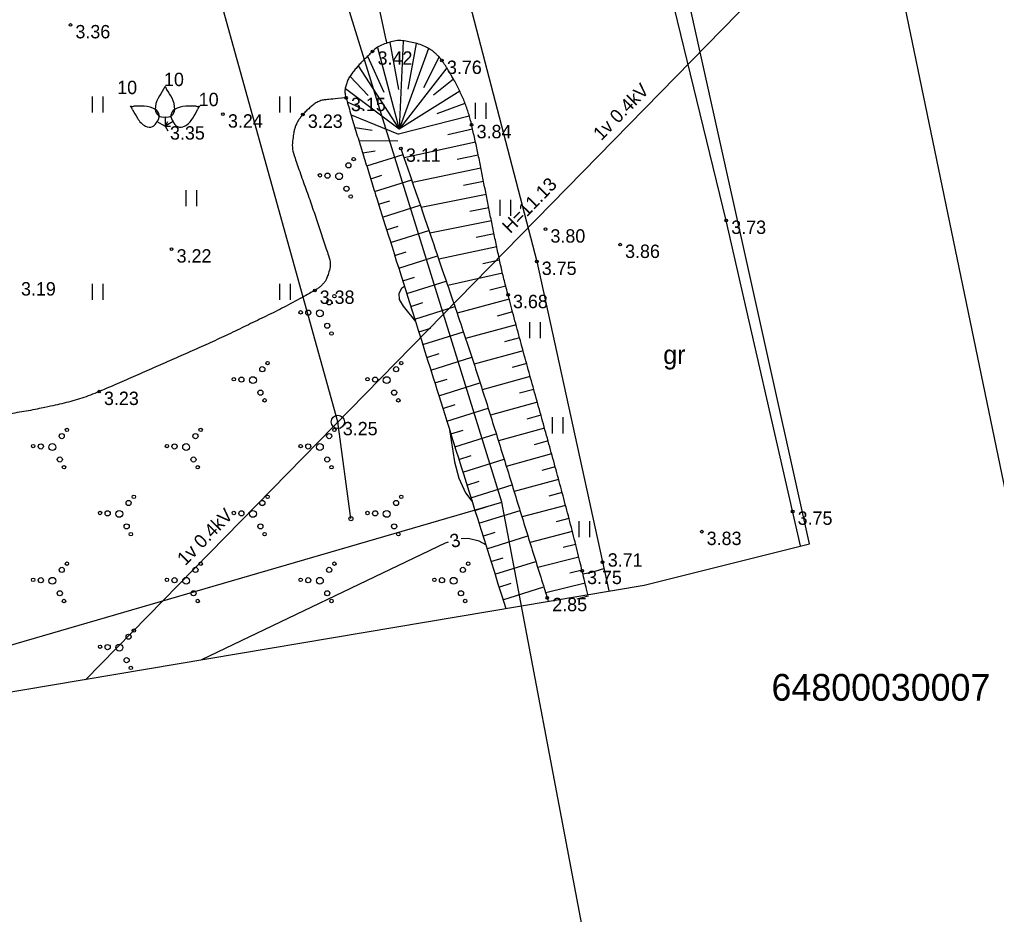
# Model space of a CAD drawing. Extents: x 321079 to 321220, y 257030 to 257220.
# Drawn here: x 321153.77 to 321190.3, y 257097.53 to 257130.98 of the extents above; entities that cross this region are included whole.
import ezdxf

# ---------------------------------------------------------------- set-up
doc = ezdxf.new("R2010")
doc.units = 0
for name, color, linetype in [('CELI_CMAL_####_####_#', 7, 'Continuous'), ('CELI_CSEG_####_TKST_#', 7, 'Continuous'), ('ELEK_ELEM_####_####_#', 7, 'Continuous'), ('ELEK_SAIT_####_####_#', 7, 'Continuous'), ('ELEK_VADV_ZSPR_####_#', 7, 'Continuous'), ('ELEK_VADV_ZSPR_TKST_#', 7, 'Continuous'), ('RAMI_UZMR_####_####_#', 7, 'Continuous'), ('RELJ_AATZ_####_TKST_#', 7, 'Continuous'), ('RELJ_ELEM_####_####_#', 7, 'Continuous'), ('RELJ_HORZ_####_TKST_#', 7, 'Continuous'), ('RELJ_HORZ_PAMT_####_#', 7, 'Continuous'), ('RELJ_HORZ_PUSH_####_#', 7, 'Continuous'), ('RELJ_NOGA_####_####_#', 7, 'Continuous'), ('RELJ_NOGL_####_####_#', 7, 'Continuous'), ('ROBZ_KADS_####_TKST_#', 7, 'Continuous'), ('ROBZ_UZMR_####_####_#', 7, 'Continuous'), ('TERT_DIAM_####_TKST_#', 7, 'Continuous'), ('TERT_ELEM_####_####_#', 7, 'Continuous'), ('TERT_KONT_####_####_#', 7, 'Continuous')]:
    doc.layers.add(name, color=color, linetype=linetype)

msp = doc.modelspace()

# ---------------------------------------------------------------- linework, layer by layer
at = {"layer": 'CELI_CMAL_####_####_#'}
for points in [[(321182.971, 257111.303), (321180.196, 257123.466), (321177.038, 257136.408), (321174.394, 257148.502), (321172.25, 257161.008)], [(321164.229, 257149.382), (321166.166, 257146.657), (321169.755, 257134.824), (321173.111, 257121.931), (321175.798, 257109.619)]]:
    msp.add_lwpolyline(points, dxfattribs=at)
at = {"layer": 'ELEK_ELEM_####_####_#'}
for centre, radius in [((321165.672, 257115.939), 0.25), ((321165.672, 257115.939), 0.0225), ((321166.162, 257112.322), 0.075)]:
    msp.add_circle(centre, radius, dxfattribs=at)
at = {"layer": 'ELEK_SAIT_####_####_#'}
msp.add_line((321166.162, 257112.322), (321165.672, 257115.939), dxfattribs=at)
at = {"layer": 'ELEK_VADV_ZSPR_####_#'}
for p, q in [((321165.672, 257115.939), (321155.067, 257154.09)), ((321190.982, 257141.796), (321156.234, 257106.297))]:
    msp.add_line(p, q, dxfattribs=at)
at = {"layer": 'RAMI_UZMR_####_####_#'}
msp.add_lwpolyline([(321107.5, 257141.5), (321108.611, 257133.395), (321131.584, 257099.382), (321150.327, 257105.322), (321177.121, 257109.842), (321183.308, 257111.386), (321177.517, 257137.442), (321172.561, 257161.05), (321156.27, 257158.872), (321156.852, 257154.517), (321139.352, 257150.329), (321114.57, 257145.337)], close=True, dxfattribs=at)
at = {"layer": 'RELJ_ELEM_####_####_#'}
for centre in [(321155.676, 257130.776), (321166.972, 257129.79), (321169.565, 257129.445), (321165.978, 257128.056), (321161.378, 257127.439), (321164.367, 257127.43), (321170.675, 257127.041), (321168.031, 257126.162), (321180.196, 257123.466), (321173.436, 257123.14), (321159.459, 257122.394), (321176.226, 257122.566), (321173.111, 257121.931), (321164.809, 257120.851), (321172.035, 257120.69), (321156.743, 257117.07), (321182.677, 257112.592), (321179.277, 257111.836), (321175.564, 257110.692), (321174.805, 257110.376), (321173.503, 257109.362)]:
    msp.add_circle(centre, 0.05, dxfattribs=at)
at = {"layer": 'RELJ_HORZ_PAMT_####_#'}
for points in [[(321169.793, 257111.444), (321169.686, 257111.408), (321160.579, 257107.051)], [(321171.203, 257111.339), (321170.955, 257111.479), (321170.543, 257111.58), (321170.279, 257111.565)]]:
    msp.add_lwpolyline(points, dxfattribs=at)
at = {"layer": 'RELJ_HORZ_PUSH_####_#'}
for points in [[(321167.176, 257131.552), (321167.47, 257130.219), (321167.505, 257130.094)], [(321168.161, 257121.006), (321168.057, 257120.93), (321167.951, 257120.735), (321167.971, 257120.513), (321168.117, 257120.265), (321168.573, 257119.697)], [(321169.85, 257115.639), (321170.038, 257114.442), (321170.191, 257113.832), (321170.451, 257113.287), (321170.688, 257112.976)], [(321174.834, 257110.255), (321175.166, 257110.321), (321175.614, 257110.462)]]:
    msp.add_lwpolyline(points, dxfattribs=at)
at = {"layer": 'RELJ_NOGA_####_####_#'}
for p, q in [((321167.617, 257130.126), (321167.936, 257128.366)), ((321168.113, 257130.169), (321167.969, 257126.878)), ((321168.605, 257130.085), (321168.284, 257128.376)), ((321166.784, 257129.605), (321167.392, 257128.259)), ((321167.158, 257129.935), (321167.969, 257126.878)), ((321169.065, 257129.892), (321167.969, 257126.878)), ((321169.455, 257129.583), (321168.876, 257128.427)), ((321166.434, 257129.248), (321167.969, 257126.878)), ((321166.134, 257128.849), (321166.808, 257128.134)), ((321169.742, 257129.174), (321167.969, 257126.878)), ((321170, 257128.746), (321169.248, 257128.149)), ((321167.969, 257126.878), (321165.964, 257128.386)), ((321170.229, 257128.302), (321167.969, 257126.878)), ((321166.026, 257127.898), (321166.64, 257127.616)), ((321170.424, 257127.842), (321169.372, 257127.455)), ((321166.17, 257127.419), (321167.942, 257126.691)), ((321170.588, 257127.37), (321167.942, 257126.691)), ((321166.314, 257126.94), (321166.956, 257126.845)), ((321170.71, 257126.885), (321169.789, 257126.666)), ((321166.458, 257126.462), (321167.913, 257126.45)), ((321170.817, 257126.397), (321168.152, 257125.807)), ((321167.073, 257126.063), (321166.605, 257125.984)), ((321166.751, 257125.506), (321168.111, 257125.929)), ((321170.922, 257125.908), (321170.136, 257125.746)), ((321171.023, 257125.418), (321168.464, 257124.892)), ((321166.9, 257125.028), (321167.311, 257125.156)), ((321167.048, 257124.551), (321168.434, 257124.982)), ((321171.121, 257124.928), (321170.371, 257124.779)), ((321167.197, 257124.073), (321167.616, 257124.204)), ((321171.218, 257124.437), (321168.784, 257123.955)), ((321167.347, 257123.596), (321168.755, 257124.039)), ((321171.315, 257123.947), (321170.605, 257123.806)), ((321171.412, 257123.456), (321169.109, 257123)), ((321167.497, 257123.119), (321167.923, 257123.253)), ((321167.647, 257122.642), (321169.078, 257123.093)), ((321171.514, 257122.967), (321170.844, 257122.826)), ((321167.797, 257122.165), (321168.23, 257122.302)), ((321171.617, 257122.477), (321169.443, 257122.022)), ((321167.947, 257121.689), (321169.401, 257122.146)), ((321171.722, 257121.989), (321171.091, 257121.845)), ((321168.097, 257121.212), (321168.537, 257121.35)), ((321168.247, 257120.735), (321169.723, 257121.199)), ((321171.833, 257121.501), (321169.78, 257121.033)), ((321171.954, 257121.016), (321171.354, 257120.866)), ((321172.078, 257120.531), (321170.129, 257120.009)), ((321168.397, 257120.258), (321168.844, 257120.398)), ((321168.548, 257119.781), (321170.046, 257120.252)), ((321172.207, 257120.048), (321171.632, 257119.894)), ((321168.698, 257119.304), (321169.15, 257119.446)), ((321172.337, 257119.566), (321170.448, 257119.059)), ((321168.848, 257118.827), (321170.365, 257119.305)), ((321172.466, 257119.083), (321171.908, 257118.933)), ((321168.998, 257118.35), (321169.456, 257118.494)), ((321169.148, 257117.873), (321170.679, 257118.355)), ((321172.599, 257118.6), (321170.763, 257118.094)), ((321172.732, 257118.118), (321172.187, 257117.968)), ((321169.298, 257117.396), (321169.758, 257117.541)), ((321172.865, 257117.636), (321171.07, 257117.141)), ((321169.448, 257116.919), (321170.986, 257117.403)), ((321172.998, 257117.154), (321172.465, 257117.007)), ((321169.598, 257116.442), (321170.06, 257116.588)), ((321169.748, 257115.965), (321171.292, 257116.451)), ((321173.131, 257116.673), (321171.375, 257116.188)), ((321173.264, 257116.191), (321172.742, 257116.046)), ((321173.397, 257115.709), (321171.673, 257115.232)), ((321169.898, 257115.488), (321170.361, 257115.634)), ((321170.048, 257115.011), (321171.591, 257115.496)), ((321173.53, 257115.227), (321173.018, 257115.085)), ((321170.198, 257114.534), (321170.66, 257114.68)), ((321173.663, 257114.745), (321171.971, 257114.277)), ((321170.348, 257114.057), (321171.888, 257114.541)), ((321173.796, 257114.263), (321173.293, 257114.124)), ((321170.498, 257113.58), (321170.96, 257113.725)), ((321170.648, 257113.103), (321172.186, 257113.587)), ((321173.928, 257113.78), (321172.262, 257113.341)), ((321174.055, 257113.297), (321173.562, 257113.167)), ((321174.183, 257112.813), (321172.56, 257112.386)), ((321170.797, 257112.626), (321171.259, 257112.771)), ((321170.947, 257112.149), (321172.484, 257112.632)), ((321174.31, 257112.33), (321173.83, 257112.203)), ((321171.097, 257111.672), (321171.558, 257111.817)), ((321174.438, 257111.846), (321172.858, 257111.43)), ((321171.247, 257111.195), (321172.781, 257111.677)), ((321174.56, 257111.362), (321174.092, 257111.246)), ((321171.397, 257110.718), (321171.857, 257110.863)), ((321171.547, 257110.241), (321173.079, 257110.722)), ((321174.681, 257110.877), (321173.149, 257110.497)), ((321174.801, 257110.391), (321174.35, 257110.279)), ((321171.697, 257109.764), (321172.156, 257109.908)), ((321174.918, 257109.905), (321173.444, 257109.55)), ((321171.847, 257109.287), (321173.376, 257109.768)), ((321175.036, 257109.419), (321174.604, 257109.315))]:
    msp.add_line(p, q, dxfattribs=at)
msp.add_open_spline([(321175.019, 257109.488), (321174.948, 257109.784), (321174.876, 257110.08), (321174.805, 257110.376), (321174.597, 257111.241), (321174.377, 257112.104), (321174.148, 257112.964), (321173.918, 257113.824), (321173.683, 257114.682), (321173.446, 257115.54), (321173.21, 257116.398), (321172.969, 257117.255), (321172.732, 257118.113), (321172.495, 257118.971), (321172.263, 257119.83), (321172.035, 257120.69), (321171.897, 257121.213), (321171.771, 257121.739), (321171.659, 257122.268), (321171.547, 257122.797), (321171.439, 257123.327), (321171.332, 257123.857), (321171.226, 257124.388), (321171.123, 257124.92), (321171.017, 257125.451), (321170.911, 257125.983), (321170.794, 257126.512), (321170.675, 257127.041), (321170.627, 257127.256), (321170.562, 257127.465), (321170.491, 257127.674), (321170.419, 257127.882), (321170.336, 257128.084), (321170.24, 257128.283), (321170.144, 257128.483), (321170.042, 257128.68), (321169.93, 257128.871), (321169.873, 257128.969), (321169.814, 257129.064), (321169.754, 257129.16), (321169.693, 257129.257), (321169.63, 257129.351), (321169.565, 257129.445), (321169.499, 257129.54), (321169.419, 257129.621), (321169.334, 257129.702), (321169.245, 257129.786), (321169.149, 257129.849), (321169.039, 257129.908), (321168.812, 257130.03), (321168.574, 257130.1), (321168.332, 257130.148), (321168.092, 257130.195), (321167.832, 257130.197), (321167.593, 257130.123), (321167.365, 257130.052), (321167.143, 257129.953), (321166.972, 257129.79), (321166.904, 257129.726), (321166.838, 257129.661), (321166.772, 257129.595), (321166.704, 257129.528), (321166.637, 257129.461), (321166.57, 257129.394), (321166.44, 257129.262), (321166.325, 257129.12), (321166.209, 257128.971), (321166.104, 257128.836), (321166.027, 257128.687), (321165.981, 257128.524), (321165.938, 257128.372), (321165.934, 257128.206), (321165.978, 257128.056), (321166.175, 257127.387), (321166.374, 257126.718), (321166.581, 257126.052), (321166.789, 257125.385), (321166.995, 257124.717), (321167.204, 257124.05), (321168.783, 257119.023), (321170.369, 257113.997), (321171.947, 257108.969)], degree=3, dxfattribs=at)
at = {"layer": 'RELJ_NOGL_####_####_#'}
msp.add_open_spline([(321168.031, 257126.162), (321168.73, 257124.114), (321169.428, 257122.065), (321170.127, 257120.017), (321170.427, 257119.135), (321170.719, 257118.25), (321171.002, 257117.363), (321171.286, 257116.476), (321171.565, 257115.587), (321171.841, 257114.698), (321172.117, 257113.808), (321172.389, 257112.917), (321172.666, 257112.028), (321172.943, 257111.139), (321173.22, 257110.249), (321173.503, 257109.362), (321173.516, 257109.321), (321173.529, 257109.28), (321173.542, 257109.239)], degree=3, dxfattribs=at)
at = {"layer": 'ROBZ_UZMR_####_####_#'}
for p, q in [((321194.114, 257096.554), (321182.887, 257150.703)), ((321171.804, 257112.938), (321162.618, 257142.549)), ((321131.975, 257101.369), (321171.804, 257112.938)), ((321176.188, 257089.762), (321171.804, 257112.938))]:
    msp.add_line(p, q, dxfattribs=at)
at = {"layer": 'TERT_ELEM_####_####_#'}
for p, q in [((321156.5, 257127.5), (321156.5, 257128.1)), ((321156.9, 257127.5), (321156.9, 257128.1)), ((321163.5, 257127.5), (321163.5, 257128.1)), ((321163.9, 257127.5), (321163.9, 257128.1)), ((321170.813, 257127.262), (321170.813, 257127.862)), ((321171.213, 257127.262), (321171.213, 257127.862)), ((321158.907, 257127.168), (321159.212, 257126.992)), ((321159.212, 257127.344), (321159.212, 257126.992)), ((321159.517, 257127.168), (321159.212, 257126.992)), ((321159.212, 257126.992), (321159.312, 257127.165)), ((321159.212, 257126.992), (321159.412, 257126.992)), ((321159.212, 257126.992), (321159.312, 257126.819)), ((321160, 257124), (321160, 257124.6)), ((321160.4, 257124), (321160.4, 257124.6)), ((321171.741, 257123.646), (321171.741, 257124.246)), ((321172.141, 257123.646), (321172.141, 257124.246)), ((321156.5, 257120.5), (321156.5, 257121.1)), ((321156.9, 257120.5), (321156.9, 257121.1)), ((321163.5, 257120.5), (321163.5, 257121.1)), ((321163.9, 257120.5), (321163.9, 257121.1)), ((321172.854, 257119.07), (321172.854, 257119.67)), ((321173.254, 257119.07), (321173.254, 257119.67)), ((321173.694, 257115.51), (321173.694, 257116.11)), ((321174.094, 257115.51), (321174.094, 257116.11)), ((321174.691, 257111.631), (321174.691, 257112.231)), ((321175.091, 257111.631), (321175.091, 257112.231))]:
    msp.add_line(p, q, dxfattribs=at)
for centre, radius in [((321166.067, 257125.53), 0.096), ((321166.263, 257125.762), 0.064), ((321165.001, 257125.157), 0.064), ((321165.285, 257125.143), 0.096), ((321165.719, 257125.122), 0.128), ((321165.995, 257124.655), 0.096), ((321166.153, 257124.366), 0.064), ((321165.348, 257120.408), 0.096), ((321165.544, 257120.639), 0.064), ((321164.282, 257120.034), 0.064), ((321164.566, 257120.021), 0.096), ((321165, 257120), 0.128), ((321165.276, 257119.533), 0.096), ((321165.434, 257119.244), 0.064), ((321162.848, 257117.908), 0.096), ((321163.044, 257118.139), 0.064), ((321167.848, 257117.908), 0.096), ((321168.044, 257118.139), 0.064), ((321161.782, 257117.534), 0.064), ((321162.066, 257117.521), 0.096), ((321162.5, 257117.5), 0.128), ((321166.782, 257117.534), 0.064), ((321167.066, 257117.521), 0.096), ((321167.5, 257117.5), 0.128), ((321162.776, 257117.033), 0.096), ((321162.934, 257116.744), 0.064), ((321167.776, 257117.033), 0.096), ((321167.934, 257116.744), 0.064), ((321155.544, 257115.639), 0.064), ((321160.544, 257115.639), 0.064), ((321165.544, 257115.639), 0.064), ((321155.348, 257115.408), 0.096), ((321160.348, 257115.408), 0.096), ((321165.348, 257115.408), 0.096), ((321154.282, 257115.034), 0.064), ((321154.566, 257115.021), 0.096), ((321155, 257115), 0.128), ((321159.282, 257115.034), 0.064), ((321159.566, 257115.021), 0.096), ((321160, 257115), 0.128), ((321164.282, 257115.034), 0.064), ((321164.566, 257115.021), 0.096), ((321165, 257115), 0.128), ((321155.276, 257114.533), 0.096), ((321160.276, 257114.533), 0.096), ((321165.276, 257114.533), 0.096), ((321155.434, 257114.244), 0.064), ((321160.434, 257114.244), 0.064), ((321165.434, 257114.244), 0.064), ((321158.044, 257113.139), 0.064), ((321163.044, 257113.139), 0.064), ((321168.044, 257113.139), 0.064), ((321157.848, 257112.908), 0.096), ((321162.848, 257112.908), 0.096), ((321167.848, 257112.908), 0.096), ((321156.782, 257112.534), 0.064), ((321157.066, 257112.521), 0.096), ((321157.5, 257112.5), 0.128), ((321161.782, 257112.534), 0.064), ((321162.066, 257112.521), 0.096), ((321162.5, 257112.5), 0.128), ((321166.782, 257112.534), 0.064), ((321167.066, 257112.521), 0.096), ((321167.5, 257112.5), 0.128), ((321157.776, 257112.033), 0.096), ((321162.776, 257112.033), 0.096), ((321167.776, 257112.033), 0.096), ((321157.934, 257111.744), 0.064), ((321162.934, 257111.744), 0.064), ((321167.934, 257111.744), 0.064), ((321155.544, 257110.639), 0.064), ((321160.544, 257110.639), 0.064), ((321165.544, 257110.639), 0.064), ((321170.544, 257110.639), 0.064), ((321155.348, 257110.408), 0.096), ((321160.348, 257110.408), 0.096), ((321165.348, 257110.408), 0.096), ((321170.348, 257110.408), 0.096), ((321154.282, 257110.034), 0.064), ((321154.566, 257110.021), 0.096), ((321155, 257110), 0.128), ((321159.282, 257110.034), 0.064), ((321159.566, 257110.021), 0.096), ((321160, 257110), 0.128), ((321164.282, 257110.034), 0.064), ((321164.566, 257110.021), 0.096), ((321165, 257110), 0.128), ((321169.282, 257110.034), 0.064), ((321169.566, 257110.021), 0.096), ((321170, 257110), 0.128), ((321155.276, 257109.533), 0.096), ((321160.276, 257109.533), 0.096), ((321165.276, 257109.533), 0.096), ((321170.276, 257109.533), 0.096), ((321155.434, 257109.244), 0.064), ((321160.434, 257109.244), 0.064), ((321165.434, 257109.244), 0.064), ((321170.434, 257109.244), 0.064), ((321158.044, 257108.139), 0.064), ((321157.848, 257107.908), 0.096), ((321156.782, 257107.534), 0.064), ((321157.066, 257107.521), 0.096), ((321157.5, 257107.5), 0.128), ((321157.776, 257107.033), 0.096), ((321157.934, 257106.744), 0.064)]:
    msp.add_circle(centre, radius, dxfattribs=at)
for centre, radius, start, end in [((321158.795, 257128.63), 0.439, 324.3837, 341.712), ((321159.629, 257128.63), 0.439, 198.288, 215.6163), ((321171.837, 257120.596), 14.88, 148.4844, 149.9901), ((321146.587, 257120.596), 14.88, 30.0099, 31.5156), ((321159.736, 257127.617), 0.89, 151.757, 179.9138), ((321158.688, 257127.617), 0.89, 0.0862, 28.243), ((321157.585, 257127.45), 0.439, 24.3837, 41.712), ((321158.002, 257128.172), 0.439, 258.288, 275.6163), ((321171.064, 257134.727), 14.88, 208.4844, 209.9901), ((321158.439, 257112.861), 14.88, 90.0099, 91.5156), ((321158.409, 257126.85), 0.89, 60.0862, 88.243), ((321159.136, 257127.623), 0.29, 181.0782, 285.2823), ((321158.703, 257127.374), 0.29, 314.7177, 58.9218), ((321159.288, 257127.623), 0.29, 254.7177, 358.9218), ((321159.721, 257127.374), 0.29, 121.0782, 225.2823), ((321160.015, 257126.85), 0.89, 91.757, 119.9138), ((321159.985, 257112.861), 14.88, 88.4844, 89.9901), ((321147.36, 257134.727), 14.88, 330.0099, 331.5156), ((321160.422, 257128.172), 0.439, 264.3837, 281.712), ((321160.839, 257127.45), 0.439, 138.288, 155.6163), ((321158.933, 257127.758), 0.89, 211.757, 239.9138), ((321158.627, 257127.242), 0.29, 241.0782, 345.2823), ((321159.797, 257127.242), 0.29, 194.7177, 298.9218), ((321159.491, 257127.758), 0.89, 300.0862, 328.243)]:
    msp.add_arc(centre, radius, start, end, dxfattribs=at)
at = {"layer": 'TERT_KONT_####_####_#'}
msp.add_open_spline([(321165.978, 257128.056), (321165.719, 257128.031), (321165.461, 257128.006), (321165.202, 257127.981), (321165.12, 257127.973), (321165.042, 257127.949), (321164.965, 257127.917), (321164.886, 257127.883), (321164.815, 257127.84), (321164.748, 257127.787), (321164.679, 257127.733), (321164.613, 257127.677), (321164.55, 257127.617), (321164.487, 257127.556), (321164.426, 257127.495), (321164.367, 257127.43), (321164.32, 257127.379), (321164.278, 257127.325), (321164.237, 257127.269), (321164.197, 257127.215), (321164.167, 257127.158), (321164.137, 257127.097), (321164.079, 257126.975), (321164.04, 257126.849), (321164.019, 257126.719), (321163.973, 257126.437), (321163.962, 257126.131), (321164.053, 257125.859), (321164.27, 257125.211), (321164.509, 257124.572), (321164.731, 257123.926), (321164.939, 257123.319), (321165.144, 257122.71), (321165.338, 257122.1), (321165.411, 257121.87), (321165.364, 257121.611), (321165.282, 257121.374), (321165.243, 257121.264), (321165.189, 257121.168), (321165.106, 257121.084), (321165.013, 257120.991), (321164.92, 257120.912), (321164.809, 257120.851), (321164.154, 257120.491), (321163.501, 257120.137), (321162.83, 257119.815), (321162.161, 257119.493), (321161.495, 257119.165), (321160.819, 257118.86), (321160.143, 257118.555), (321159.465, 257118.255), (321158.786, 257117.955), (321158.107, 257117.655), (321157.426, 257117.361), (321156.743, 257117.07), (321156.425, 257116.935), (321156.099, 257116.819), (321155.766, 257116.727), (321155.437, 257116.635), (321155.104, 257116.564), (321154.771, 257116.492), (321154.105, 257116.348), (321153.431, 257116.25), (321152.764, 257116.107), (321152.083, 257115.96), (321151.428, 257115.734), (321150.792, 257115.429), (321150.449, 257115.264), (321150.137, 257115.062), (321149.841, 257114.828), (321149.681, 257114.702), (321149.525, 257114.575), (321149.378, 257114.436), (321149.301, 257114.363), (321149.224, 257114.289), (321149.15, 257114.213), (321149.112, 257114.174), (321149.074, 257114.135), (321149.037, 257114.095), (321149.018, 257114.075), (321149, 257114.054), (321148.981, 257114.034), (321148.962, 257114.014), (321148.944, 257113.993), (321148.925, 257113.972), (321148.844, 257113.881), (321148.769, 257113.785), (321148.695, 257113.687), (321148.626, 257113.596), (321148.567, 257113.499), (321148.509, 257113.4), (321148.4, 257113.214), (321148.316, 257113.027), (321148.252, 257112.817), (321148.132, 257112.422), (321148.07, 257112.027), (321148.101, 257111.632), (321148.133, 257111.233), (321148.178, 257110.834), (321148.243, 257110.436), (321148.308, 257110.038), (321148.394, 257109.647), (321148.447, 257109.249), (321148.641, 257107.803), (321148.836, 257106.357), (321149.03, 257104.911)], degree=3, dxfattribs=at)

# ---------------------------------------------------------------- texts
at = {"layer": 'CELI_CSEG_####_TKST_#'}
msp.add_text('gr', height=0.7, dxfattribs=at).set_placement((321177.839, 257118.103))
at = {"layer": 'ELEK_VADV_ZSPR_TKST_#'}
for s, p in [('1v 0.4kV', (321175.522, 257126.431)), ('H=11.13', (321172.121, 257122.956)), ('1v 0.4kV', (321159.968, 257110.54))]:
    msp.add_text(s, height=0.5, rotation=45.6124, dxfattribs=at).set_placement(p)
at = {"layer": 'RELJ_AATZ_####_TKST_#'}
for s, p in [(' 3.36', (321155.676, 257130.276)), (' 3.42', (321166.972, 257129.29)), (' 3.76', (321169.565, 257128.945)), (' 3.15', (321165.978, 257127.556)), (' 3.24', (321161.378, 257126.939)), (' 3.23', (321164.367, 257126.93)), (' 3.84', (321170.675, 257126.541)), (' 3.35', (321159.212, 257126.492)), (' 3.11', (321168.031, 257125.662)), (' 3.73', (321180.196, 257122.966)), (' 3.80', (321173.436, 257122.64)), (' 3.22', (321159.459, 257121.894)), (' 3.86', (321176.226, 257122.066)), (' 3.75', (321173.111, 257121.431)), (' 3.19', (321153.641, 257120.663)), (' 3.38', (321164.809, 257120.351)), (' 3.68', (321172.035, 257120.19)), (' 3.23', (321156.743, 257116.57)), (' 3.25', (321165.672, 257115.439)), (' 3.75', (321182.677, 257112.092)), (' 3.83', (321179.277, 257111.336)), (' 3.71', (321175.579, 257110.528)), (' 3.75', (321174.805, 257109.876)), (' 2.85', (321173.503, 257108.862))]:
    msp.add_text(s, height=0.5, dxfattribs=at).set_placement(p)
at = {"layer": 'RELJ_HORZ_####_TKST_#'}
msp.add_text('3', height=0.5, rotation=13.9772, dxfattribs=at).set_placement((321169.933, 257111.221))
at = {"layer": 'ROBZ_KADS_####_TKST_#'}
msp.add_text('64800030007', height=1, dxfattribs=at).set_placement((321181.886, 257105.518))
at = {"layer": 'TERT_DIAM_####_TKST_#'}
for p in [(321158.987, 257128.492), (321157.238, 257128.192), (321160.286, 257127.742)]:
    msp.add_text(' 10', height=0.5, dxfattribs=at).set_placement(p)

doc.saveas('drawing.dxf')
